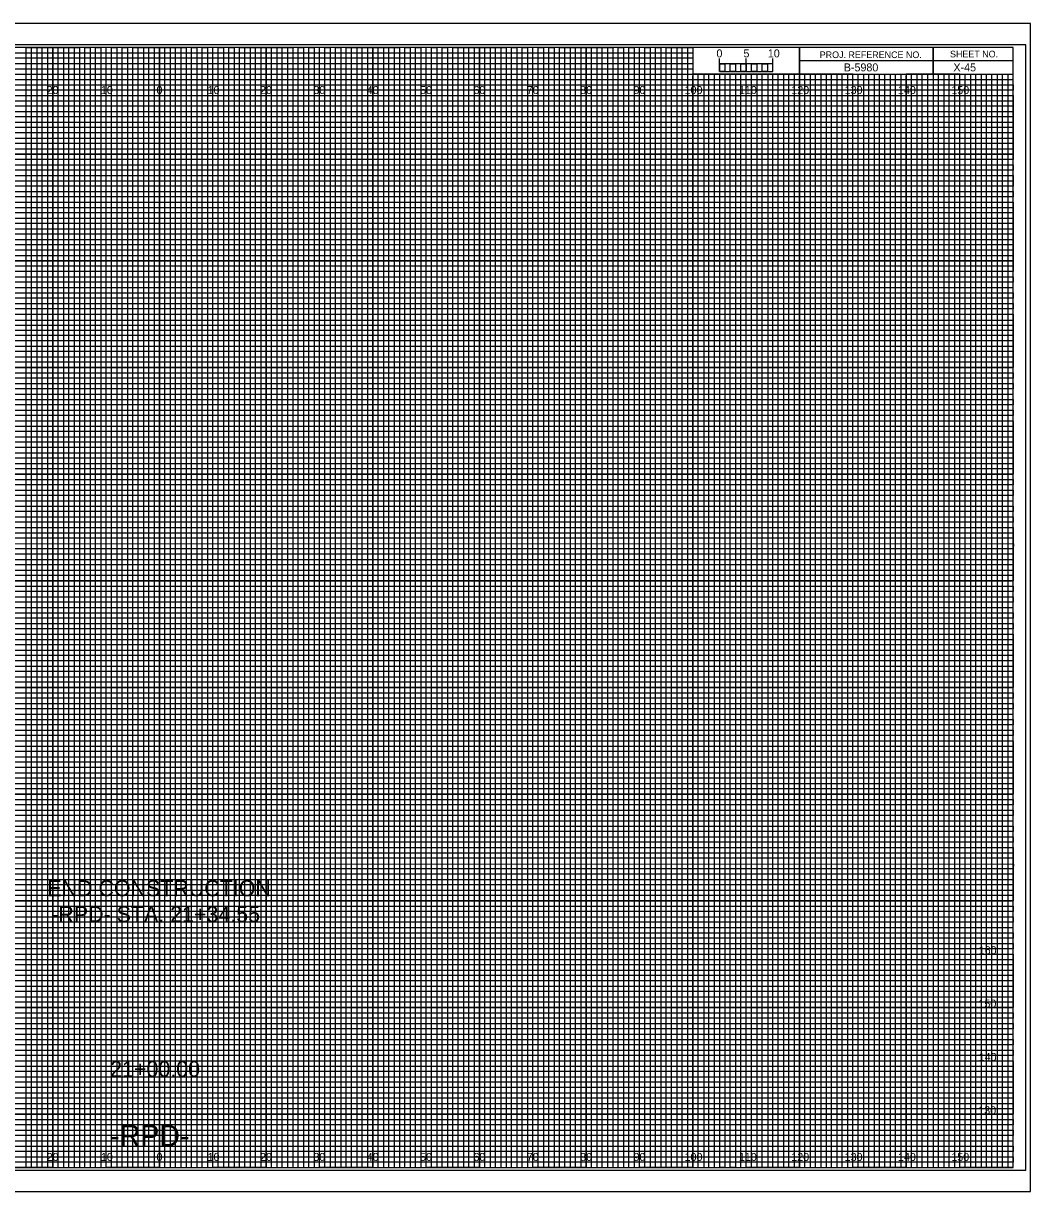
# Model space of a CAD drawing. Extents: x -13 to 323, y -5 to 874.
# Drawn here: x 134.5 to 323.3, y 655.5 to 874.5 of the extents above; entities that cross this region are included whole.
import ezdxf

# ---------------------------------------------------------------- set-up
doc = ezdxf.new("R2010")
doc.units = 0
for name, color, linetype in [('Exist Cross Section Cell', 7, 'Continuous'), ('Exist XS Center Line Elevation Label', 7, 'Continuous'), ('Exist XS Ground Line', 7, 'Continuous'), ('Prop CMT Conc Surface', 7, 'Continuous'), ('Prop CMT Concrete Structures', 7, 'Continuous'), ('Prop CMT Pvmt Course 1', 7, 'Continuous'), ('Prop CMT Pvmt Course 1 CG', 7, 'Continuous'), ('Prop CMT Pvmt Course 2', 7, 'Continuous'), ('Prop CMT Pvmt Course 3', 7, 'Continuous'), ('Prop CMT Pvmt Surface', 7, 'Continuous'), ('Prop CMT Pvmt Surface Shoulder', 7, 'Continuous'), ('Prop CMT Shld Paved Course 1', 7, 'Continuous'), ('Prop CMT Shld Paved Course 2', 7, 'Continuous'), ('Prop CMT Shld Paved Course 3', 7, 'Continuous'), ('Prop CMT Slope Grass', 7, 'Continuous'), ('Prop CMT Subgrade Earthwork', 7, 'Continuous'), ('Scratch_Level_1', 7, 'Continuous')]:
    doc.layers.add(name, color=color, linetype=linetype)

msp = doc.modelspace()

# ---------------------------------------------------------------- linework, layer by layer
at = {"layer": 'Exist XS Center Line Elevation Label'}
for points in [[(125, 660), (135, 660), (135, 870), (145, 870), (145, 660), (155, 660), (155, 870), (165, 870), (165, 660), (175, 660), (175, 870), (185, 870), (185, 660), (195, 660), (195, 870), (205, 870), (205, 660), (215, 660), (215, 870), (225, 870), (225, 660), (235, 660), (235, 870), (245, 870), (245, 660), (255, 660), (255, 870), (259.93, 870), (260, 870), (260, 865), (264.99, 865), (264.99, 660), (275, 660), (275, 865), (285, 865), (285, 660), (295, 660), (295, 865), (305, 865), (305, 660), (315, 660), (315, 865)], [(0, 865), (275, 865)], [(0, 845), (320, 845), (320, 855), (0, 855)], [(0, 825), (320, 825), (320, 835), (0, 835)], [(0, 805), (320, 805), (320, 815), (0, 815)], [(0, 785), (320, 785), (320, 795), (0, 795)], [(0, 765), (320, 765), (320, 775), (0, 775)], [(0, 745), (320, 745), (320, 755), (0, 755)], [(0, 725), (320, 725), (320, 735), (0, 735)], [(0, 705), (320, 705), (320, 715), (0, 715)], [(0, 685), (320, 685), (320, 695), (0, 695)], [(0, 665), (320, 665), (320, 675), (0, 675)]]:
    msp.add_lwpolyline(points, dxfattribs=at)
at = {"layer": 'Exist XS Ground Line'}
for p, q in [((150, 870), (140, 870)), ((140, 870), (140, 660)), ((150, 660), (150, 870)), ((170, 870), (160, 870)), ((160, 870), (160, 660)), ((170, 660), (170, 870)), ((190, 870), (180, 870)), ((180, 870), (180, 660)), ((190, 660), (190, 870)), ((210, 870), (200, 870)), ((200, 870), (200, 660)), ((210, 660), (210, 870)), ((230, 870), (220, 870)), ((220, 870), (220, 660)), ((230, 660), (230, 870)), ((250, 870), (240, 870)), ((240, 870), (240, 660)), ((250, 660), (250, 870)), ((260, 870), (260, 660)), ((270, 660), (270, 865)), ((290, 865), (280, 865)), ((280, 865), (280, 660)), ((290, 660), (290, 865)), ((310, 865), (300, 865)), ((300, 865), (300, 660)), ((310, 660), (310, 865)), ((140, 660), (130, 660)), ((160, 660), (150, 660)), ((180, 660), (170, 660)), ((200, 660), (190, 660)), ((220, 660), (210, 660)), ((240, 660), (230, 660)), ((260, 660), (250, 660)), ((280, 660), (270, 660)), ((300, 660), (290, 660)), ((320, 660), (310, 660)), ((320, 660), (320, 660))]:
    msp.add_line(p, q, dxfattribs=at)
for points in [[(0, 860), (320, 860), (320, 850), (0, 850)], [(0, 840), (320, 840), (320, 830), (0, 830)], [(0, 820), (320, 820), (320, 810), (0, 810)], [(0, 800), (320, 800), (320, 790), (0, 790)], [(0, 780), (320, 780), (320, 770), (0, 770)], [(0, 760), (320, 760), (320, 750), (0, 750)], [(0, 740), (320, 740), (320, 730), (0, 730)], [(0, 720), (320, 720), (320, 710), (0, 710)], [(0, 700), (320, 700), (320, 690), (0, 690)], [(0, 680), (320, 680), (320, 670), (0, 670)]]:
    msp.add_lwpolyline(points, dxfattribs=at)
at = {"layer": 'Prop CMT Pvmt Course 2'}
for p, q in [((265, 865.49), (265, 867.9)), ((265, 866.9), (265, 867.9)), ((270, 865.49), (270, 867.9)), ((275, 865.49), (275, 867.9)), ((275, 866.9), (275, 867.9))]:
    msp.add_line(p, q, dxfattribs=at)
for points in [[(275, 866.9), (265, 866.9), (265, 865.49), (275, 865.49)], [(265, 866.9), (266, 866.9), (266, 865.49), (265, 865.49)], [(267, 866.9), (268, 866.9), (268, 865.49), (267, 865.49)], [(269, 866.9), (270, 866.9), (270, 865.49), (269, 865.49)], [(271, 866.9), (272, 866.9), (272, 865.49), (271, 865.49)], [(273, 866.9), (274, 866.9), (274, 865.49), (273, 865.49)]]:
    msp.add_lwpolyline(points, close=True, dxfattribs=at)
at = {"layer": 'Prop CMT Pvmt Course 3'}
msp.add_lwpolyline([(-13.4, 655.5), (323.3, 655.5), (323.3, 874.5), (-13.4, 874.5)], close=True, dxfattribs=at)
at = {"layer": 'Prop CMT Pvmt Surface'}
for p, q in [((140, 660), (140, 870)), ((150, 660), (150, 870)), ((160, 660), (160, 870)), ((170, 660), (170, 870)), ((180, 660), (180, 870)), ((190, 660), (190, 870)), ((200, 660), (200, 870)), ((210, 660), (210, 870)), ((220, 660), (220, 870)), ((230, 660), (230, 870)), ((240, 660), (240, 870)), ((250, 660), (250, 870)), ((260, 660), (260, 864.69)), ((270, 660), (270, 864.69)), ((280, 660), (280, 864.69)), ((290, 660), (290, 864.69)), ((300, 660), (300, 864.69)), ((310, 660), (310, 864.69)), ((0, 860), (320, 860)), ((0, 850), (320, 850)), ((0, 840), (320, 840)), ((0, 830), (320, 830)), ((0, 820), (320, 820)), ((0, 810), (320, 810)), ((0, 800), (320, 800)), ((0, 790), (320, 790)), ((0, 780), (320, 780)), ((0, 770), (320, 770)), ((0, 760), (320, 760)), ((0, 750), (320, 750)), ((0, 740), (320, 740)), ((0, 730), (320, 730)), ((0, 720), (320, 720)), ((0, 710), (320, 710)), ((0, 700), (320, 700)), ((0, 690), (320, 690)), ((0, 680), (320, 680)), ((0, 670), (320, 670))]:
    msp.add_line(p, q, dxfattribs=at)
at = {"layer": 'Prop CMT Pvmt Surface Shoulder'}
for p, q in [((323.3, 874.5), (-13.4, 874.5)), ((-13.4, 655.5), (323.3, 655.5))]:
    msp.add_line(p, q, dxfattribs=at)
at = {"layer": 'Prop CMT Shld Paved Course 1'}
for p, q in [((0, 869), (260, 869)), ((260, 867.98), (0, 867.98)), ((260, 869), (260, 867.98)), ((0, 867), (260, 867)), ((260, 865.89), (0, 865.89)), ((260, 867), (260, 865.89)), ((0, 864), (320, 864))]:
    msp.add_line(p, q, dxfattribs=at)
for points in [[(0, 863), (270, 863), (320, 863), (320, 862), (0, 862)], [(0, 861), (320, 861), (320, 859), (0, 859)], [(0, 858), (320, 858), (320, 857), (0, 856.98)], [(0, 856), (320, 856), (320, 854), (0, 854)], [(0, 853), (320, 853), (320, 852), (0, 852)], [(0, 851), (320, 851), (320, 849), (0, 849)], [(0, 848), (320, 848), (320, 847), (0, 847)], [(0, 846), (320, 846), (320, 844), (0, 844)], [(0, 843), (320, 843), (320, 842), (0, 842)], [(0, 841), (320, 841), (320, 839), (0, 839)], [(0, 838), (320, 838), (320, 837), (0, 837)], [(0, 836), (320, 836), (320, 833.95), (320, 833), (320, 832), (0, 832)], [(0, 834), (320, 834), (320, 833), (0, 833)], [(0, 831), (320, 831), (320, 829), (0, 829.03)], [(0, 829.03), (320, 829), (320, 828), (0, 828)], [(0, 827), (320, 827), (320, 826), (0, 826)], [(0, 824), (320, 824), (320, 823), (0, 823)], [(0, 822), (320, 822), (320, 821), (0, 821)], [(-0.07, 818.89), (320, 818.89), (320, 817.88), (-0.07, 817.88)], [(0, 817), (320, 817), (320, 816), (0, 816)], [(0, 814), (320, 814), (320, 813), (0, 813)], [(0, 812), (320, 812), (320, 811), (0, 811)], [(0, 809), (320, 809), (320, 808), (0, 808)], [(0, 807), (320, 807), (320, 806), (0, 806)], [(0, 804), (320, 804), (320, 803), (0, 803)], [(0, 802), (320, 802), (320, 801), (0, 801)], [(0, 799), (320, 799), (319.99, 797.98), (0, 798)], [(0, 797), (320, 797), (320, 796), (0, 796)], [(0, 794), (320, 794), (320, 793), (0, 793)], [(0, 792), (320, 792), (320, 791), (0, 791)], [(0, 789), (320, 789), (320, 788), (0, 788)], [(0, 787), (320, 787), (320, 786), (0, 786)], [(0, 784), (320, 784), (320, 783), (0, 783)], [(0, 782), (320, 782), (320, 781), (0, 781)], [(0, 779), (320, 779), (320, 778), (0, 778)], [(0, 776.99), (320.07, 776.91), (320, 776), (0, 776)], [(0, 774), (320, 774), (320, 773), (0, 773)], [(0, 772), (320, 772), (320, 771), (0, 771)], [(0, 769), (320, 769), (320, 768), (0, 768)], [(0, 767), (320, 767), (320, 766), (0, 766)], [(0, 764), (320, 764), (320, 763), (0, 763)], [(0, 762), (320, 762), (320, 761), (0, 761)], [(0, 759), (320, 759), (320, 758), (0, 758)], [(0, 757), (320, 757), (320, 756), (0, 756)], [(0, 754), (320, 754), (320, 753), (0, 753)], [(0, 752), (320, 752), (320, 751), (0, 751)], [(0, 749), (320, 749), (320, 748), (0, 748)], [(0, 747), (320, 747), (320, 746), (0, 746)], [(0, 744), (320, 744), (320, 743), (0, 743)], [(0, 742), (320, 742), (320, 741), (0, 741)], [(0, 739), (320, 739), (319.99, 737.98), (0, 738)], [(0, 737), (320, 737), (320, 736), (0, 736)], [(0, 734), (320, 734), (320, 733), (0, 733)], [(0, 732), (320, 732), (320, 731), (0, 731)], [(0, 729), (320, 729), (320, 728), (0, 728)], [(0, 727), (320, 727), (320, 726), (0, 726)], [(0, 724), (320, 724), (320, 723), (0, 723)], [(0, 722), (320, 722), (320, 721), (0, 721)], [(0, 719), (320, 719), (320, 718), (0, 718)], [(0, 716.99), (320.07, 716.91), (320, 716), (0, 716)], [(0, 714), (320, 714), (320, 713), (0, 713)], [(0, 712), (320, 712), (320, 711), (0, 711)], [(0, 709), (320, 709), (320, 708), (0, 708)], [(0, 707), (320, 707), (320, 706), (0, 706)], [(0, 704), (320, 704), (320, 703), (0, 703)], [(0, 702), (320, 702), (320, 701), (0, 701)], [(0, 699), (320, 699), (320, 698), (0, 698)], [(0, 697), (320, 697), (320, 696), (0, 696)], [(0, 694), (320, 694), (320, 693), (0, 693)], [(0, 692), (320, 692), (320, 691), (0, 691)], [(0, 689), (320, 689), (320, 688), (0, 688)], [(0, 687), (320, 687), (320, 686), (0, 686)], [(0, 684), (320, 684), (320, 683), (0, 683)], [(0, 682), (320, 682), (320, 681), (0, 681)], [(0, 679), (320, 679), (320, 678), (0, 678)], [(0, 677), (320, 677), (320, 676), (0, 676)], [(0, 674), (320, 674), (320, 673), (0, 673)], [(0, 672), (320, 672), (320, 671), (0, 671)], [(0, 669), (320, 669), (320, 668), (0, 668)], [(0, 667), (320, 667), (320, 666), (0, 666)], [(0, 664), (320, 664), (320, 663), (0, 663)], [(0, 662), (320, 662), (320, 661), (0, 661)]]:
    msp.add_lwpolyline(points, dxfattribs=at)
at = {"layer": 'Prop CMT Shld Paved Course 2'}
for p, q in [((305, 870), (305, 865)), ((305, 865), (305, 870)), ((280, 867.5), (280, 865)), ((320, 867.49), (280, 867.49)), ((280, 865), (320, 865))]:
    msp.add_line(p, q, dxfattribs=at)
for points in [[(320, 870), (0, 870), (0, 660), (320, 660)], [(280, 870), (260, 870), (260, 865.03), (280, 865.03)], [(320, 870), (280, 870), (280, 865), (320, 865)]]:
    msp.add_lwpolyline(points, close=True, dxfattribs=at)
at = {"layer": 'Prop CMT Shld Paved Course 3'}
for p, q in [((267, 865), (266.01, 865)), ((266.01, 865), (266.01, 660)), ((267, 660), (267, 865)), ((269, 865), (268, 865)), ((268, 865), (268, 660)), ((269, 660), (269, 865)), ((266.01, 660), (265, 660)), ((268, 660), (267, 660))]:
    msp.add_line(p, q, dxfattribs=at)
for points in [[(135, 660), (136, 660), (136, 870), (137, 870), (137, 660)], [(137, 660), (138, 660), (138, 870), (139, 870), (139, 660)], [(140, 660), (141, 660), (141, 870), (142, 870), (142, 660)], [(142, 660), (143, 660), (143, 870), (144, 870), (144, 660)], [(145, 660), (146, 660), (146, 870), (147, 870), (147, 660)], [(147, 660), (148, 660), (148, 870), (149, 870), (149, 660)], [(150, 660), (151, 660), (151, 870), (152, 870), (152, 660)], [(152, 660), (153, 660), (153, 870), (154, 870), (154, 660)], [(155, 660), (156, 660), (156, 870), (157, 870), (157, 660)], [(157, 660), (158, 660), (158, 870), (159, 870), (159, 660)], [(160, 660), (161, 660), (161, 870), (162, 870), (162, 660)], [(162, 660), (163, 660), (163, 870), (164, 870), (164, 660)], [(165, 660), (166, 660), (166, 870), (167, 870), (167, 660)], [(167, 660), (168, 660), (168, 870), (169, 870), (169, 660)], [(170, 660), (171, 660), (171, 870), (172, 870), (172, 660)], [(172, 660), (173, 660), (173, 870), (174, 870), (174, 660)], [(175, 660), (176, 660), (176, 870), (177, 870), (177, 660)], [(177, 660), (178, 660), (178, 870), (179, 870), (179, 660)], [(180, 660), (181, 660), (181, 870), (182, 870), (182, 660)], [(182, 660), (183, 660), (183, 870), (184, 870), (184, 660)], [(185, 660), (186, 660), (186, 870), (187, 870), (187, 660)], [(187, 660), (188, 660), (188, 870), (189, 870), (189, 660)], [(190, 660), (191, 660), (191, 870), (192, 870), (192, 660)], [(192, 660), (193, 660), (193, 870), (194, 870), (194, 660)], [(195, 660), (196, 660), (196, 870), (197, 870), (197, 660)], [(197, 660), (198, 660), (198, 870), (199, 870), (199, 660)], [(200, 660), (201, 660), (201, 870), (202, 870), (202, 660)], [(202, 660), (203, 660), (203, 870), (204, 870), (204, 660)], [(205, 660), (206, 660), (206, 870), (207, 870), (207, 660)], [(207, 660), (208, 660), (208, 870), (209, 870), (209, 660)], [(210, 660), (211, 660), (211, 870), (212, 870), (212, 660)], [(212, 660), (213, 660), (213, 870), (214, 870), (214, 660)], [(215, 660), (216, 660), (216, 870), (217, 870), (217, 660)], [(217, 660), (218, 660), (218, 870), (219, 870), (219, 660)], [(220, 660), (221, 660), (221, 870), (222, 870), (222, 660)], [(222, 660), (223, 660), (223, 870), (224, 870), (224, 660)], [(225, 660), (226, 660), (226, 870), (227, 870), (227, 660)], [(227, 660), (228, 660), (228, 870), (229, 870), (229, 660)], [(230, 660), (231, 660), (231, 870), (232, 870), (232, 660)], [(232, 660), (233, 660), (233, 870), (234, 870), (234, 660)], [(235, 660), (236, 660), (236, 870), (237, 870), (237, 660)], [(237, 660), (238, 660), (238, 870), (239, 870), (239, 660)], [(240, 660), (241, 660), (241, 870), (242, 870), (242, 660)], [(242, 660), (243, 660), (243, 870), (244, 870), (244, 660)], [(245, 660), (246, 660), (246, 870), (247, 870), (247, 660)], [(247, 660), (248, 660), (248, 870), (249, 870), (249, 660)], [(250, 660), (251, 660), (251, 870), (252, 870), (252, 660)], [(252, 660), (253, 660), (253, 870), (254, 870), (254, 660)], [(255, 660), (256, 660), (256, 870), (257, 870), (257, 660)], [(257, 660), (258, 660), (258, 870), (259, 870), (259, 660)], [(260, 660), (261, 660), (261, 865), (262.02, 865), (262.02, 660)], [(262, 660), (263, 660), (263, 865), (263.99, 865), (263.99, 660)], [(270, 660), (270.98, 660), (270.98, 865), (272, 865), (272, 660)], [(272, 660), (273, 660), (273, 865), (274.05, 865), (274.05, 660)], [(275, 660), (276, 660), (276, 865), (277, 865), (277, 660)], [(277, 660), (278, 660), (278, 865), (279, 865), (279, 660)], [(280, 660), (281, 660), (281, 865), (282, 865), (282, 660)], [(282, 660), (283, 660), (283, 865), (284, 865), (284, 660)], [(285, 660), (286, 660), (286, 865), (287, 865), (287, 660)], [(287, 660), (288, 660), (288, 865), (289, 865), (289, 660)], [(290, 660), (291, 660), (291, 865), (292, 865), (292, 660)], [(292, 660), (293, 660), (293, 865), (294, 865), (294, 660)], [(295, 660), (296, 660), (296, 865), (297, 865), (297, 660)], [(297, 660), (298, 660), (298, 865), (299, 865), (299, 660)], [(300, 660), (301, 660), (301, 865), (302, 865), (302, 660)], [(302, 660), (303, 660), (303, 865), (304, 865), (304, 660)], [(305, 660), (306, 660), (306, 865), (307, 865), (307, 660)], [(307, 660), (308, 660), (308, 865), (309, 865), (309, 660)], [(310, 660), (311, 660), (311, 865), (312, 865), (312, 660)], [(312, 660), (313, 660), (313, 865), (314, 865), (314, 660)], [(315, 660), (316, 660), (316, 865), (317, 865), (317, 660)], [(317, 660), (318, 660), (318, 865), (319, 865), (319, 660)]]:
    msp.add_lwpolyline(points, dxfattribs=at)
at = {"layer": 'Prop CMT Subgrade Earthwork'}
msp.add_lwpolyline([(-10.8, 659.5), (322.4, 659.5), (322.4, 870.5), (-10.8, 870.5)], close=True, dxfattribs=at)

# ---------------------------------------------------------------- texts
at = {"layer": 'Exist Cross Section Cell'}
for s, p in [('20', (138.86, 861.25)), ('10', (149.04, 861.25)), ('0', (159.45, 861.25)), ('0', (159.45, 861.25)), ('10', (169.04, 861.25)), ('20', (178.86, 861.25)), ('30', (188.86, 861.25)), ('40', (198.86, 861.25)), ('50', (208.86, 861.25)), ('60', (218.86, 861.25)), ('70', (228.86, 861.25)), ('80', (238.86, 861.25)), ('90', (248.86, 861.25)), ('100', (258.44, 861.25)), ('110', (268.62, 861.25)), ('120', (278.44, 861.25)), ('130', (288.44, 861.25)), ('140', (298.44, 861.25)), ('150', (308.44, 861.25)), ('20', (138.86, 661.25)), ('10', (149.04, 661.25)), ('0', (159.45, 661.25)), ('0', (159.45, 661.25)), ('10', (169.04, 661.25)), ('20', (178.86, 661.25)), ('30', (188.86, 661.25)), ('40', (198.86, 661.25)), ('50', (208.86, 661.25)), ('60', (218.86, 661.25)), ('70', (228.86, 661.25)), ('80', (238.86, 661.25)), ('90', (248.86, 661.25)), ('100', (258.44, 661.25)), ('110', (268.62, 661.25)), ('120', (278.44, 661.25)), ('130', (288.44, 661.25)), ('140', (298.44, 661.25)), ('150', (308.44, 661.25))]:
    msp.add_text(s, height=1.5, dxfattribs=at).set_placement(p)
at = {"layer": 'Prop CMT Conc Surface'}
for s, p in [('5', (269.47, 868.12)), ('10', (274.04, 868.12))]:
    msp.add_text(s, height=1.5, dxfattribs=at).set_placement(p)
at = {"layer": 'Prop CMT Concrete Structures'}
msp.add_text('B-5980', height=1.5, dxfattribs=at).set_placement((288.28, 865.5))
at = {"layer": 'Prop CMT Pvmt Course 1'}
for s, p in [('160', (313.57, 700)), ('150', (313.52, 690)), ('140', (313.57, 680)), ('130', (313.49, 670))]:
    msp.add_text(s, height=1.5, dxfattribs=at).set_placement(p)
at = {"layer": 'Prop CMT Pvmt Course 1 CG'}
msp.add_text('-RPD-', height=4, dxfattribs=at).set_placement((150.78, 664))
at = {"layer": 'Prop CMT Pvmt Course 2'}
msp.add_text('0', height=1.5, dxfattribs=at).set_placement((264.41, 868.12))
at = {"layer": 'Prop CMT Shld Paved Course 2'}
for s, p in [('PROJ. REFERENCE NO.', (283.77, 867.99)), ('SHEET NO.', (308.19, 868.12))]:
    msp.add_text(s, height=1.25, dxfattribs=at).set_placement(p)
at = {"layer": 'Prop CMT Slope Grass'}
for s, p in [('END CONSTRUCTION', (138.99, 710.88)), ('-RPD- STA. 21+34.55', (139.73, 706.01)), ('21+00.00', (150.77, 676.99))]:
    msp.add_text(s, height=3, dxfattribs=at).set_placement(p)
at = {"layer": 'Scratch_Level_1'}
msp.add_text('X-45', height=1.5, dxfattribs=at).set_placement((308.83, 865.5))

doc.saveas('drawing.dxf')
